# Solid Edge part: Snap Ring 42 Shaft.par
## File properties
Title: Snap Ring 42 Shaft
Author: Dan
Template: Normal.par
Last saved by: Dan
Revision: 11
Application: Solid Edge
Material: steel
Density: 0 kg/mm^3
Accuracy: 0.99
Document Number: P52-010
Project Name: Piston Pump P52
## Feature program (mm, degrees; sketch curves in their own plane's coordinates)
sketch for "unnamed Protrusion 1" plane through (0, 0, 0) normal (0, 0, 1) x-axis (1, 0, 0)
  line (-8.6805, 21.2991) -> (-8.6805, 18.018)
  arc centre (0, 0) radius 20 from (8.6805, 18.018) to (-8.6805, 18.018) cw
  line (8.6805, 21.299) -> (8.6805, 18.018)
  arc centre (0, 0) radius 23 from (8.6805, 21.299) to (-8.6805, 21.2991) cw
extrude "unnamed Protrusion 1" add finite 1.2 along +normal
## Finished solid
Body 1: solid body, 6 faces, 12 edges, 8 vertices.
  Faces by surface: plane 4, cylinder 2
  Edges by curve: line 8, circle 4
Bounding box of the edges (mm): 46.000 x 44.299 x 1.200, from (-23, -23, 0) to (23, 21.2991, 1.2).
Cylindrical faces by radius (mm): R20 x1, R23 x1
Planar faces by outward normal: +x 1, +z 1, -x 1, -z 1
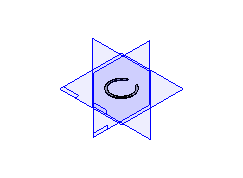
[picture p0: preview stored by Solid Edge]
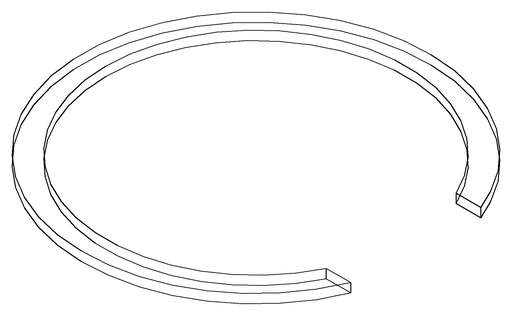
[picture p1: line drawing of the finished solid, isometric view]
